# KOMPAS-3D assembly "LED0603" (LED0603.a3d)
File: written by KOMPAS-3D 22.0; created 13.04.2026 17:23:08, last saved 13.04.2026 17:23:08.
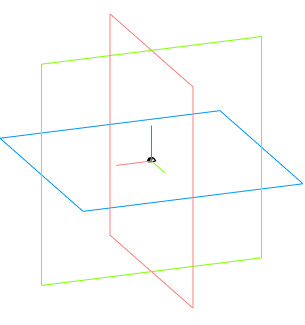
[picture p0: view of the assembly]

Document properties: Автор: Andrey; Полное имя файла: C:\Users\User1\Documents\LED0603.a3d

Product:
- Component [detail]: V0603-SMD-R (Red)  | qty 1  | source file: V0603-SMD-R (Red).m3d
- Part/product: LED0603
    Комментарий: LED0603

Referenced files in C:\Users\User1\Documents\: V0603-SMD-R (Red).m3d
